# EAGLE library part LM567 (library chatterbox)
Tone Decoder
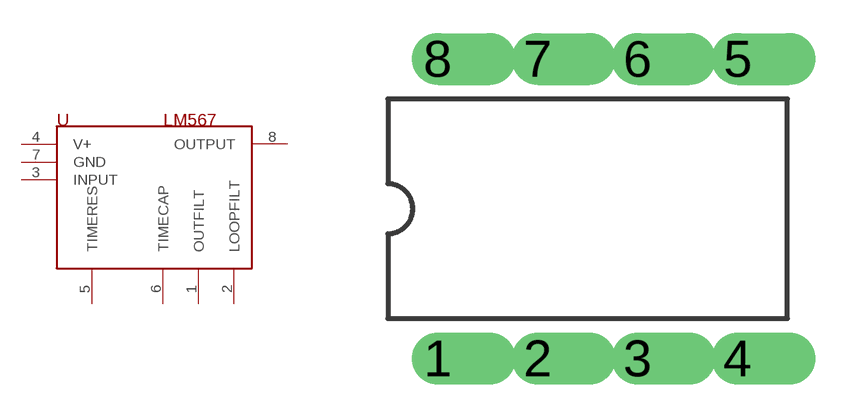
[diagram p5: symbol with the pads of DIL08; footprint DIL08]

Designator prefix -

## LM567C  [DIL08]
1  OUTFILT  pas
2  LOOPFILT  pas
3  INPUT  in
4  V+  pwr
5  TIMERES  pas
6  TIMECAP  pas
7  GND  pwr
8  OUTPUT  pas

## Footprint DIL08 (pad centres in mm)
Dual In Line 8
drill 0.813 offset: 1 -3.81,-3.81; 2 -1.27,-3.81; 3 1.27,-3.81; 4 3.81,-3.81; 5 3.81,3.81; 6 1.27,3.81; 7 -1.27,3.81; 8 -3.81,3.81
